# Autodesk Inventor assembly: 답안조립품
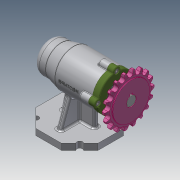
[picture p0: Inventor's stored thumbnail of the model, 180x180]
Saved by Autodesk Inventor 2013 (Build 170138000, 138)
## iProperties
Created: 2021-01
Part Number: 답안조립품
Document SubType Name: Assembly
Designer: user
Author: user
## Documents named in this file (12)
- C:\Users\user\Desktop\710106V1002\답안조립품.iam
- C:\Users\user\Desktop\710106V1002\본체.ipt
- C:\Users\user\Desktop\710106V1002\키 5 x 5 x 14.ipt
- C:\Users\user\Desktop\710106V1002\커버.ipt
- C:\Users\user\Desktop\710106V1002\축.ipt
- C:\Users\user\Desktop\710106V1002\오일 실.ipt
- C:\Users\user\Desktop\710106V1002\어댑터슬리브.ipt
- C:\Users\user\Desktop\710106V1002\스프로킷.ipt
- C:\Users\user\Desktop\710106V1002\볼트 M4.ipt
- C:\Users\user\Desktop\710106V1002\베어링 51202.ipt
- C:\Users\user\Desktop\710106V1002\베어링 6004.ipt
- C:\Users\user\Desktop\710106V1002\멈춤나사 M3.ipt
